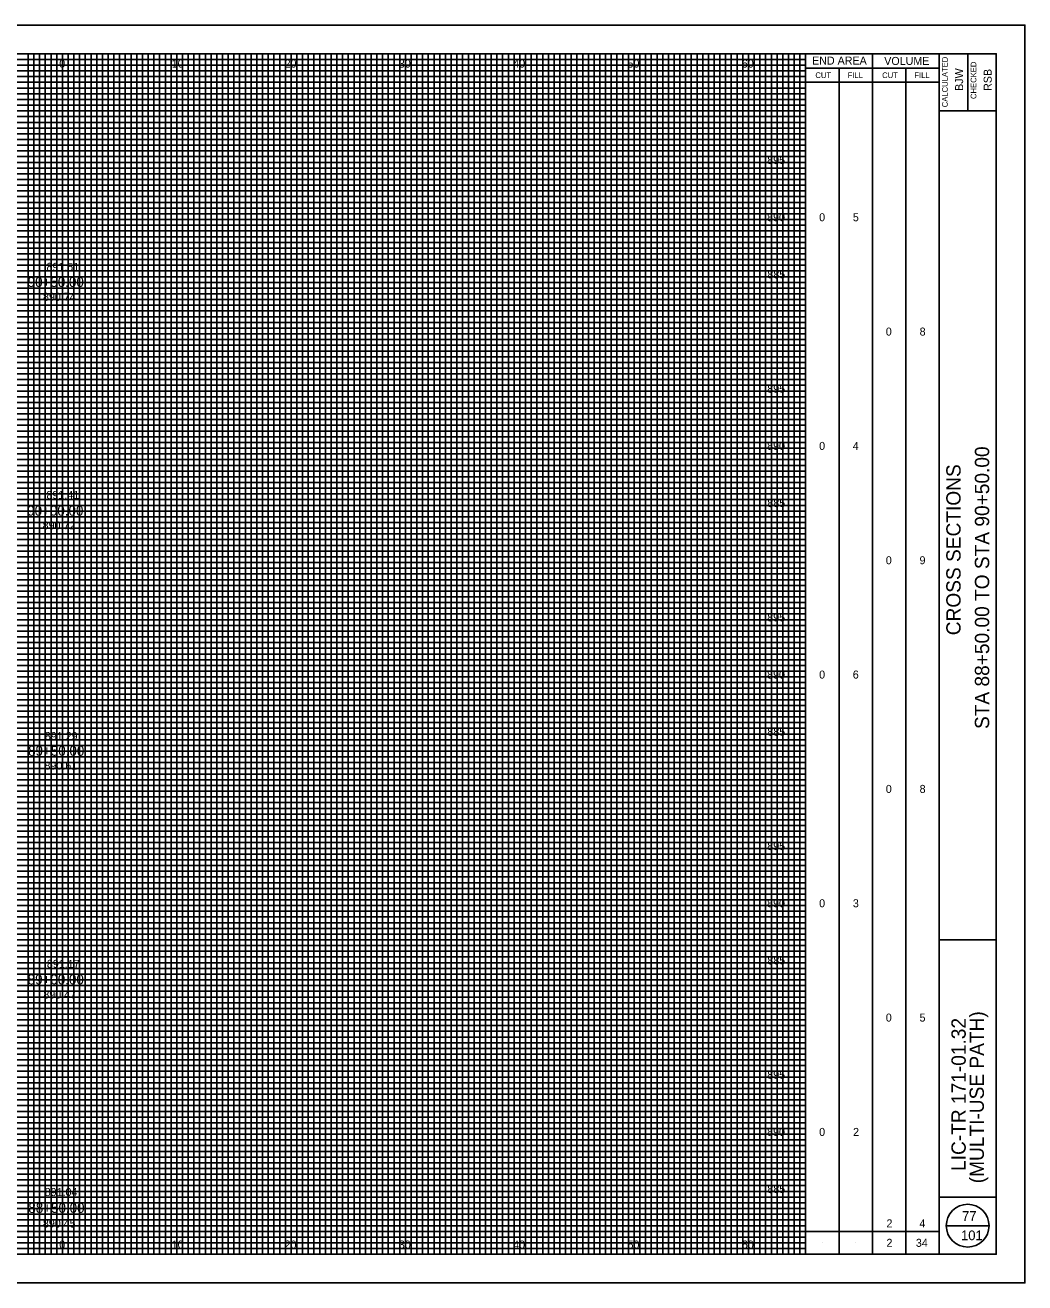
# Model space of a CAD drawing. Extents: x -10 to 160, y -2 to 3672.
# Drawn here: x 72.6 to 160, y 917.5 to 1027.5 of the extents above; entities that cross this region are included whole.
import ezdxf

# ---------------------------------------------------------------- set-up
doc = ezdxf.new("R2010")
doc.units = 0
for name, color, linetype in [('SH_Border', 7, 'Continuous'), ('SH_Cut_Line', 7, 'Continuous'), ('SH_Data', 7, 'Continuous'), ('SH_Major_Grid_Line', 7, 'Continuous'), ('SH_Minor_Grid_Line', 7, 'Continuous'), ('SH_Text', 7, 'Continuous'), ('TX_P_10', 7, 'Continuous'), ('TX_X_10', 7, 'Continuous')]:
    doc.layers.add(name, color=color, linetype=linetype)

msp = doc.modelspace()

# ---------------------------------------------------------------- linework, layer by layer
at = {"layer": 'SH_Border'}
for p, q in [((152.5, 920), (152.5, 1025)), ((155, 1025), (155, 1020)), ((152.5, 1020), (157.5, 1020)), ((152.5, 947.5), (157.5, 947.5)), ((152.5, 925), (157.5, 925))]:
    msp.add_line(p, q, dxfattribs=at)
msp.add_lwpolyline([(0, 1025), (157.5, 1025), (157.5, 920), (0, 920)], close=True, dxfattribs=at)
at = {"layer": 'SH_Cut_Line'}
msp.add_lwpolyline([(-10, 917.5), (160, 917.5), (160, 1027.5), (-10, 1027.5)], close=True, dxfattribs=at)
at = {"layer": 'SH_Data'}
for p, q in [((140.83, 920), (140.83, 1025)), ((146.67, 920), (146.67, 1025)), ((140.83, 1023.75), (152.5, 1023.75)), ((143.75, 920), (143.75, 1023.75)), ((149.58, 920), (149.58, 1023.75)), ((140.83, 1022.5), (152.5, 1022.5)), ((140.83, 922), (152.5, 922)), ((153.12, 922.5), (156.88, 922.5)), ((142.29, 921), (142.29, 921)), ((145.21, 921), (145.21, 921)), ((148.12, 921), (148.12, 921)), ((151.04, 921), (151.04, 921))]:
    msp.add_line(p, q, dxfattribs=at)
msp.add_circle((155, 922.5), 1.87, dxfattribs=at)
at = {"layer": 'SH_Major_Grid_Line'}
for p, q in [((75.83, 920), (75.83, 1025)), ((80.83, 920), (80.83, 1025)), ((85.83, 920), (85.83, 1025)), ((90.83, 920), (90.83, 1025)), ((95.83, 920), (95.83, 1025)), ((100.83, 920), (100.83, 1025)), ((105.83, 920), (105.83, 1025)), ((110.83, 920), (110.83, 1025)), ((115.83, 920), (115.83, 1025)), ((120.83, 920), (120.83, 1025)), ((125.83, 920), (125.83, 1025)), ((130.83, 920), (130.83, 1025)), ((135.83, 920), (135.83, 1025)), ((5.83, 1020), (140.83, 1020)), ((5.83, 1015), (140.83, 1015)), ((5.83, 1010), (140.83, 1010)), ((5.83, 1005), (140.83, 1005)), ((5.83, 1000), (140.83, 1000)), ((5.83, 995), (140.83, 995)), ((5.83, 990), (140.83, 990)), ((5.83, 985), (140.83, 985)), ((5.83, 980), (140.83, 980)), ((5.83, 975), (140.83, 975)), ((5.83, 970), (140.83, 970)), ((5.83, 965), (140.83, 965)), ((5.83, 960), (140.83, 960)), ((5.83, 955), (140.83, 955)), ((5.83, 950), (140.83, 950)), ((5.83, 945), (140.83, 945)), ((5.83, 940), (140.83, 940)), ((5.83, 935), (140.83, 935)), ((5.83, 930), (140.83, 930)), ((5.83, 925), (140.83, 925))]:
    msp.add_line(p, q, dxfattribs=at)
at = {"layer": 'SH_Minor_Grid_Line'}
for p, q in [((5.83, 1024.5), (140.83, 1024.5)), ((72.83, 920), (72.83, 1025)), ((73.33, 920), (73.33, 1025)), ((73.83, 920), (73.83, 1025)), ((74.33, 920), (74.33, 1025)), ((74.83, 920), (74.83, 1025)), ((75.33, 920), (75.33, 1025)), ((76.33, 920), (76.33, 1025)), ((76.83, 920), (76.83, 1025)), ((77.33, 920), (77.33, 1025)), ((77.83, 920), (77.83, 1025)), ((78.33, 920), (78.33, 1025)), ((78.83, 920), (78.83, 1025)), ((79.33, 920), (79.33, 1025)), ((79.83, 920), (79.83, 1025)), ((80.33, 920), (80.33, 1025)), ((81.33, 920), (81.33, 1025)), ((81.83, 920), (81.83, 1025)), ((82.33, 920), (82.33, 1025)), ((82.83, 920), (82.83, 1025)), ((83.33, 920), (83.33, 1025)), ((83.83, 920), (83.83, 1025)), ((84.33, 920), (84.33, 1025)), ((84.83, 920), (84.83, 1025)), ((85.33, 920), (85.33, 1025)), ((86.33, 920), (86.33, 1025)), ((86.83, 920), (86.83, 1025)), ((87.33, 920), (87.33, 1025)), ((87.83, 920), (87.83, 1025)), ((88.33, 920), (88.33, 1025)), ((88.83, 920), (88.83, 1025)), ((89.33, 920), (89.33, 1025)), ((89.83, 920), (89.83, 1025)), ((90.33, 920), (90.33, 1025)), ((91.33, 920), (91.33, 1025)), ((91.83, 920), (91.83, 1025)), ((92.33, 920), (92.33, 1025)), ((92.83, 920), (92.83, 1025)), ((93.33, 920), (93.33, 1025)), ((93.83, 920), (93.83, 1025)), ((94.33, 920), (94.33, 1025)), ((94.83, 920), (94.83, 1025)), ((95.33, 920), (95.33, 1025)), ((96.33, 920), (96.33, 1025)), ((96.83, 920), (96.83, 1025)), ((97.33, 920), (97.33, 1025)), ((97.83, 920), (97.83, 1025)), ((98.33, 920), (98.33, 1025)), ((98.83, 920), (98.83, 1025)), ((99.33, 920), (99.33, 1025)), ((99.83, 920), (99.83, 1025)), ((100.33, 920), (100.33, 1025)), ((101.33, 920), (101.33, 1025)), ((101.83, 920), (101.83, 1025)), ((102.33, 920), (102.33, 1025)), ((102.83, 920), (102.83, 1025)), ((103.33, 920), (103.33, 1025)), ((103.83, 920), (103.83, 1025)), ((104.33, 920), (104.33, 1025)), ((104.83, 920), (104.83, 1025)), ((105.33, 920), (105.33, 1025)), ((106.33, 920), (106.33, 1025)), ((106.83, 920), (106.83, 1025)), ((107.33, 920), (107.33, 1025)), ((107.83, 920), (107.83, 1025)), ((108.33, 920), (108.33, 1025)), ((108.83, 920), (108.83, 1025)), ((109.33, 920), (109.33, 1025)), ((109.83, 920), (109.83, 1025)), ((110.33, 920), (110.33, 1025)), ((111.33, 920), (111.33, 1025)), ((111.83, 920), (111.83, 1025)), ((112.33, 920), (112.33, 1025)), ((112.83, 920), (112.83, 1025)), ((113.33, 920), (113.33, 1025)), ((113.83, 920), (113.83, 1025)), ((114.33, 920), (114.33, 1025)), ((114.83, 920), (114.83, 1025)), ((115.33, 920), (115.33, 1025)), ((116.33, 920), (116.33, 1025)), ((116.83, 920), (116.83, 1025)), ((117.33, 920), (117.33, 1025)), ((117.83, 920), (117.83, 1025)), ((118.33, 920), (118.33, 1025)), ((118.83, 920), (118.83, 1025)), ((119.33, 920), (119.33, 1025)), ((119.83, 920), (119.83, 1025)), ((120.33, 920), (120.33, 1025)), ((121.33, 920), (121.33, 1025)), ((121.83, 920), (121.83, 1025)), ((122.33, 920), (122.33, 1025)), ((122.83, 920), (122.83, 1025)), ((123.33, 920), (123.33, 1025)), ((123.83, 920), (123.83, 1025)), ((124.33, 920), (124.33, 1025)), ((124.83, 920), (124.83, 1025)), ((125.33, 920), (125.33, 1025)), ((126.33, 920), (126.33, 1025)), ((126.83, 920), (126.83, 1025)), ((127.33, 920), (127.33, 1025)), ((127.83, 920), (127.83, 1025)), ((128.33, 920), (128.33, 1025)), ((128.83, 920), (128.83, 1025)), ((129.33, 920), (129.33, 1025)), ((129.83, 920), (129.83, 1025)), ((130.33, 920), (130.33, 1025)), ((131.33, 920), (131.33, 1025)), ((131.83, 920), (131.83, 1025)), ((132.33, 920), (132.33, 1025)), ((132.83, 920), (132.83, 1025)), ((133.33, 920), (133.33, 1025)), ((133.83, 920), (133.83, 1025)), ((134.33, 920), (134.33, 1025)), ((134.83, 920), (134.83, 1025)), ((135.33, 920), (135.33, 1025)), ((136.33, 920), (136.33, 1025)), ((136.83, 920), (136.83, 1025)), ((137.33, 920), (137.33, 1025)), ((137.83, 920), (137.83, 1025)), ((138.33, 920), (138.33, 1025)), ((138.83, 920), (138.83, 1025)), ((139.33, 920), (139.33, 1025)), ((139.83, 920), (139.83, 1025)), ((140.33, 920), (140.33, 1025)), ((5.83, 1024), (140.83, 1024)), ((5.83, 1023.5), (140.83, 1023.5)), ((5.83, 1023), (140.83, 1023)), ((5.83, 1022.5), (140.83, 1022.5)), ((5.83, 1022), (140.83, 1022)), ((5.83, 1021.5), (140.83, 1021.5)), ((5.83, 1021), (140.83, 1021)), ((5.83, 1020.5), (140.83, 1020.5)), ((5.83, 1019.5), (140.83, 1019.5)), ((5.83, 1019), (140.83, 1019)), ((5.83, 1018.5), (140.83, 1018.5)), ((5.83, 1018), (140.83, 1018)), ((5.83, 1017.5), (140.83, 1017.5)), ((5.83, 1017), (140.83, 1017)), ((5.83, 1016.5), (140.83, 1016.5)), ((5.83, 1016), (140.83, 1016)), ((5.83, 1015.5), (140.83, 1015.5)), ((5.83, 1014.5), (140.83, 1014.5)), ((5.83, 1014), (140.83, 1014)), ((5.83, 1013.5), (140.83, 1013.5)), ((5.83, 1013), (140.83, 1013)), ((5.83, 1012.5), (140.83, 1012.5)), ((5.83, 1012), (140.83, 1012)), ((5.83, 1011.5), (140.83, 1011.5)), ((5.83, 1011), (140.83, 1011)), ((5.83, 1010.5), (140.83, 1010.5)), ((5.83, 1009.5), (140.83, 1009.5)), ((5.83, 1009), (140.83, 1009)), ((5.83, 1008.5), (140.83, 1008.5)), ((5.83, 1008), (140.83, 1008)), ((5.83, 1007.5), (140.83, 1007.5)), ((5.83, 1007), (140.83, 1007)), ((5.83, 1006.5), (140.83, 1006.5)), ((5.83, 1006), (140.83, 1006)), ((5.83, 1005.5), (140.83, 1005.5)), ((5.83, 1004.5), (140.83, 1004.5)), ((5.83, 1004), (140.83, 1004)), ((5.83, 1003.5), (140.83, 1003.5)), ((5.83, 1003), (140.83, 1003)), ((5.83, 1002.5), (140.83, 1002.5)), ((5.83, 1002), (140.83, 1002)), ((5.83, 1001.5), (140.83, 1001.5)), ((5.83, 1001), (140.83, 1001)), ((5.83, 1000.5), (140.83, 1000.5)), ((5.83, 999.5), (140.83, 999.5)), ((5.83, 999), (140.83, 999)), ((5.83, 998.5), (140.83, 998.5)), ((5.83, 998), (140.83, 998)), ((5.83, 997.5), (140.83, 997.5)), ((5.83, 997), (140.83, 997)), ((5.83, 996.5), (140.83, 996.5)), ((5.83, 996), (140.83, 996)), ((5.83, 995.5), (140.83, 995.5)), ((5.83, 994.5), (140.83, 994.5)), ((5.83, 994), (140.83, 994)), ((5.83, 993.5), (140.83, 993.5)), ((5.83, 993), (140.83, 993)), ((5.83, 992.5), (140.83, 992.5)), ((5.83, 992), (140.83, 992)), ((5.83, 991.5), (140.83, 991.5)), ((5.83, 991), (140.83, 991)), ((5.83, 990.5), (140.83, 990.5)), ((5.83, 989.5), (140.83, 989.5)), ((5.83, 989), (140.83, 989)), ((5.83, 988.5), (140.83, 988.5)), ((5.83, 988), (140.83, 988)), ((5.83, 987.5), (140.83, 987.5)), ((5.83, 987), (140.83, 987)), ((5.83, 986.5), (140.83, 986.5)), ((5.83, 986), (140.83, 986)), ((5.83, 985.5), (140.83, 985.5)), ((5.83, 984.5), (140.83, 984.5)), ((5.83, 984), (140.83, 984)), ((5.83, 983.5), (140.83, 983.5)), ((5.83, 983), (140.83, 983)), ((5.83, 982.5), (140.83, 982.5)), ((5.83, 982), (140.83, 982)), ((5.83, 981.5), (140.83, 981.5)), ((5.83, 981), (140.83, 981)), ((5.83, 980.5), (140.83, 980.5)), ((5.83, 979.5), (140.83, 979.5)), ((5.83, 979), (140.83, 979)), ((5.83, 978.5), (140.83, 978.5)), ((5.83, 978), (140.83, 978)), ((5.83, 977.5), (140.83, 977.5)), ((5.83, 977), (140.83, 977)), ((5.83, 976.5), (140.83, 976.5)), ((5.83, 976), (140.83, 976)), ((5.83, 975.5), (140.83, 975.5)), ((5.83, 974.5), (140.83, 974.5)), ((5.83, 974), (140.83, 974)), ((5.83, 973.5), (140.83, 973.5)), ((5.83, 973), (140.83, 973)), ((5.83, 972.5), (140.83, 972.5)), ((5.83, 972), (140.83, 972)), ((5.83, 971.5), (140.83, 971.5)), ((5.83, 971), (140.83, 971)), ((5.83, 970.5), (140.83, 970.5)), ((5.83, 969.5), (140.83, 969.5)), ((5.83, 969), (140.83, 969)), ((5.83, 968.5), (140.83, 968.5)), ((5.83, 968), (140.83, 968)), ((5.83, 967.5), (140.83, 967.5)), ((5.83, 967), (140.83, 967)), ((5.83, 966.5), (140.83, 966.5)), ((5.83, 966), (140.83, 966)), ((5.83, 965.5), (140.83, 965.5)), ((5.83, 964.5), (140.83, 964.5)), ((5.83, 964), (140.83, 964)), ((5.83, 963.5), (140.83, 963.5)), ((5.83, 963), (140.83, 963)), ((5.83, 962.5), (140.83, 962.5)), ((5.83, 962), (140.83, 962)), ((5.83, 961.5), (140.83, 961.5)), ((5.83, 961), (140.83, 961)), ((5.83, 960.5), (140.83, 960.5)), ((5.83, 959.5), (140.83, 959.5)), ((5.83, 959), (140.83, 959)), ((5.83, 958.5), (140.83, 958.5)), ((5.83, 958), (140.83, 958)), ((5.83, 957.5), (140.83, 957.5)), ((5.83, 957), (140.83, 957)), ((5.83, 956.5), (140.83, 956.5)), ((5.83, 956), (140.83, 956)), ((5.83, 955.5), (140.83, 955.5)), ((5.83, 954.5), (140.83, 954.5)), ((5.83, 954), (140.83, 954)), ((5.83, 953.5), (140.83, 953.5)), ((5.83, 953), (140.83, 953)), ((5.83, 952.5), (140.83, 952.5)), ((5.83, 952), (140.83, 952)), ((5.83, 951.5), (140.83, 951.5)), ((5.83, 951), (140.83, 951)), ((5.83, 950.5), (140.83, 950.5)), ((5.83, 949.5), (140.83, 949.5)), ((5.83, 949), (140.83, 949)), ((5.83, 948.5), (140.83, 948.5)), ((5.83, 948), (140.83, 948)), ((5.83, 947.5), (140.83, 947.5)), ((5.83, 947), (140.83, 947)), ((5.83, 946.5), (140.83, 946.5)), ((5.83, 946), (140.83, 946)), ((5.83, 945.5), (140.83, 945.5)), ((5.83, 944.5), (140.83, 944.5)), ((5.83, 944), (140.83, 944)), ((5.83, 943.5), (140.83, 943.5)), ((5.83, 943), (140.83, 943)), ((5.83, 942.5), (140.83, 942.5)), ((5.83, 942), (140.83, 942)), ((5.83, 941.5), (140.83, 941.5)), ((5.83, 941), (140.83, 941)), ((5.83, 940.5), (140.83, 940.5)), ((5.83, 939.5), (140.83, 939.5)), ((5.83, 939), (140.83, 939)), ((5.83, 938.5), (140.83, 938.5)), ((5.83, 938), (140.83, 938)), ((5.83, 937.5), (140.83, 937.5)), ((5.83, 937), (140.83, 937)), ((5.83, 936.5), (140.83, 936.5)), ((5.83, 936), (140.83, 936)), ((5.83, 935.5), (140.83, 935.5)), ((5.83, 934.5), (140.83, 934.5)), ((5.83, 934), (140.83, 934)), ((5.83, 933.5), (140.83, 933.5)), ((5.83, 933), (140.83, 933)), ((5.83, 932.5), (140.83, 932.5)), ((5.83, 932), (140.83, 932)), ((5.83, 931.5), (140.83, 931.5)), ((5.83, 931), (140.83, 931)), ((5.83, 930.5), (140.83, 930.5)), ((5.83, 929.5), (140.83, 929.5)), ((5.83, 929), (140.83, 929)), ((5.83, 928.5), (140.83, 928.5)), ((5.83, 928), (140.83, 928)), ((5.83, 927.5), (140.83, 927.5)), ((5.83, 927), (140.83, 927)), ((5.83, 926.5), (140.83, 926.5)), ((5.83, 926), (140.83, 926)), ((5.83, 925.5), (140.83, 925.5)), ((5.83, 924.5), (140.83, 924.5)), ((5.83, 924), (140.83, 924)), ((5.83, 923.5), (140.83, 923.5)), ((5.83, 923), (140.83, 923)), ((5.83, 922.5), (140.83, 922.5)), ((5.83, 922), (140.83, 922)), ((5.83, 921.5), (140.83, 921.5)), ((5.83, 921), (140.83, 921)), ((5.83, 920.5), (140.83, 920.5))]:
    msp.add_line(p, q, dxfattribs=at)

# ---------------------------------------------------------------- texts
at = {"layer": 'SH_Data'}
for s, height, p in [('END AREA', 0.7, (141.39, 1024.05)), ('VOLUME', 0.7, (147.7, 1024.02)), ('CUT', 0.5, (141.68, 1022.87)), ('FILL', 0.5, (144.5, 1022.87)), ('CUT', 0.5, (147.52, 1022.87)), ('FILL', 0.5, (150.34, 1022.87)), ('77', 0.85, (154.51, 922.92)), ('101', 0.85, (154.42, 921.23))]:
    msp.add_text(s, height=height, dxfattribs=at).set_placement(p)
for s, height, p in [('CALCULATED', 0.5, (153.26, 1020.32)), ('CHECKED', 0.5, (155.76, 1021.04)), ('BJW', 0.7, (154.6, 1021.75)), ('RSB', 0.7, (157.1, 1021.75)), ('STA 88+50.00 TO STA 90+50.00', 1.25, (156.88, 965.94)), ('CROSS SECTIONS', 1.25, (154.38, 974.14)), ('LIC-TR 171-01.32', 1.25, (154.83, 927.29)), ('(MULTI-USE PATH)', 1.25, (156.42, 926.21))]:
    msp.add_text(s, height=height, rotation=90, dxfattribs=at).set_placement(p)
at = {"layer": 'SH_Text'}
for s, height, p in [('0', 0.7, (75.55, 1023.79)), ('10', 0.7, (85.39, 1023.79)), ('20', 0.7, (95.26, 1023.79)), ('30', 0.7, (105.25, 1023.79)), ('40', 0.7, (115.25, 1023.79)), ('50', 0.7, (125.25, 1023.79)), ('60', 0.7, (135.25, 1023.79)), ('895', 0.7, (137.47, 1015.35)), ('890', 0.7, (137.46, 1010.35)), ('0', 0.7, (142.01, 1010.35)), ('5', 0.7, (144.96, 1010.35)), ('90+50.00', 0.875, (72.79, 1004.6)), ('885', 0.7, (137.48, 1005.35)), ('0', 0.7, (147.84, 1000.35)), ('8', 0.7, (150.8, 1000.35)), ('895', 0.7, (137.47, 995.35)), ('890', 0.7, (137.46, 990.35)), ('0', 0.7, (142.01, 990.35)), ('4', 0.7, (144.95, 990.35)), ('885', 0.7, (137.48, 985.35)), ('90+00.00', 0.875, (72.75, 984.6)), ('0', 0.7, (147.84, 980.35)), ('9', 0.7, (150.79, 980.35)), ('895', 0.7, (137.47, 975.35)), ('890', 0.7, (137.46, 970.35)), ('0', 0.7, (142.01, 970.35)), ('6', 0.7, (144.95, 970.35)), ('885', 0.7, (137.48, 965.35)), ('89+50.00', 0.875, (72.83, 963.6)), ('0', 0.7, (147.84, 960.35)), ('8', 0.7, (150.8, 960.35)), ('895', 0.7, (137.47, 955.35)), ('890', 0.7, (137.46, 950.35)), ('0', 0.7, (142.01, 950.35)), ('3', 0.7, (144.96, 950.35)), ('885', 0.7, (137.48, 945.35)), ('89+00.00', 0.875, (72.79, 943.6)), ('0', 0.7, (147.84, 940.35)), ('5', 0.7, (150.79, 940.35)), ('895', 0.7, (137.47, 935.35)), ('890', 0.7, (137.46, 930.35)), ('0', 0.7, (142.01, 930.35)), ('2', 0.7, (144.98, 930.35)), ('885', 0.7, (137.48, 925.35)), ('88+50.00', 0.875, (72.85, 923.62)), ('2', 0.7, (147.9, 922.35)), ('4', 0.7, (150.78, 922.35)), ('0', 0.7, (75.55, 920.5)), ('10', 0.7, (85.39, 920.5)), ('20', 0.7, (95.26, 920.5)), ('30', 0.7, (105.25, 920.5)), ('40', 0.7, (115.25, 920.5)), ('50', 0.7, (125.25, 920.5)), ('60', 0.7, (135.25, 920.5)), ('2', 0.7, (147.9, 920.65)), ('34', 0.7, (150.47, 920.65))]:
    msp.add_text(s, height=height, dxfattribs=at).set_placement(p)
at = {"layer": 'TX_P_10'}
for s, p in [('891.51', (74.43, 1006.01)), ('891.41', (74.43, 986.06)), ('891.29', (74.29, 964.97)), ('891.17', (74.47, 945.05)), ('891.04', (74.28, 925.09))]:
    msp.add_text(s, height=0.7, dxfattribs=at).set_placement(p)
at = {"layer": 'TX_X_10'}
for s, p in [('890.74', (74.13, 1003.39)), ('890.72', (74.1, 983.4)), ('890.61', (74.26, 962.39)), ('890.47', (74.16, 942.37)), ('890.45', (74.12, 922.34))]:
    msp.add_text(s, height=0.7, dxfattribs=at).set_placement(p)

doc.saveas('drawing.dxf')
